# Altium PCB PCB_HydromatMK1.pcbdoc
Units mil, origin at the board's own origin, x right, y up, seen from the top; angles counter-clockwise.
Board outline 5065 x 4705 mil, 2 copper layers (Top Layer, Bottom Layer); 78 components, 51 nets, 249 pads, 533 vias.
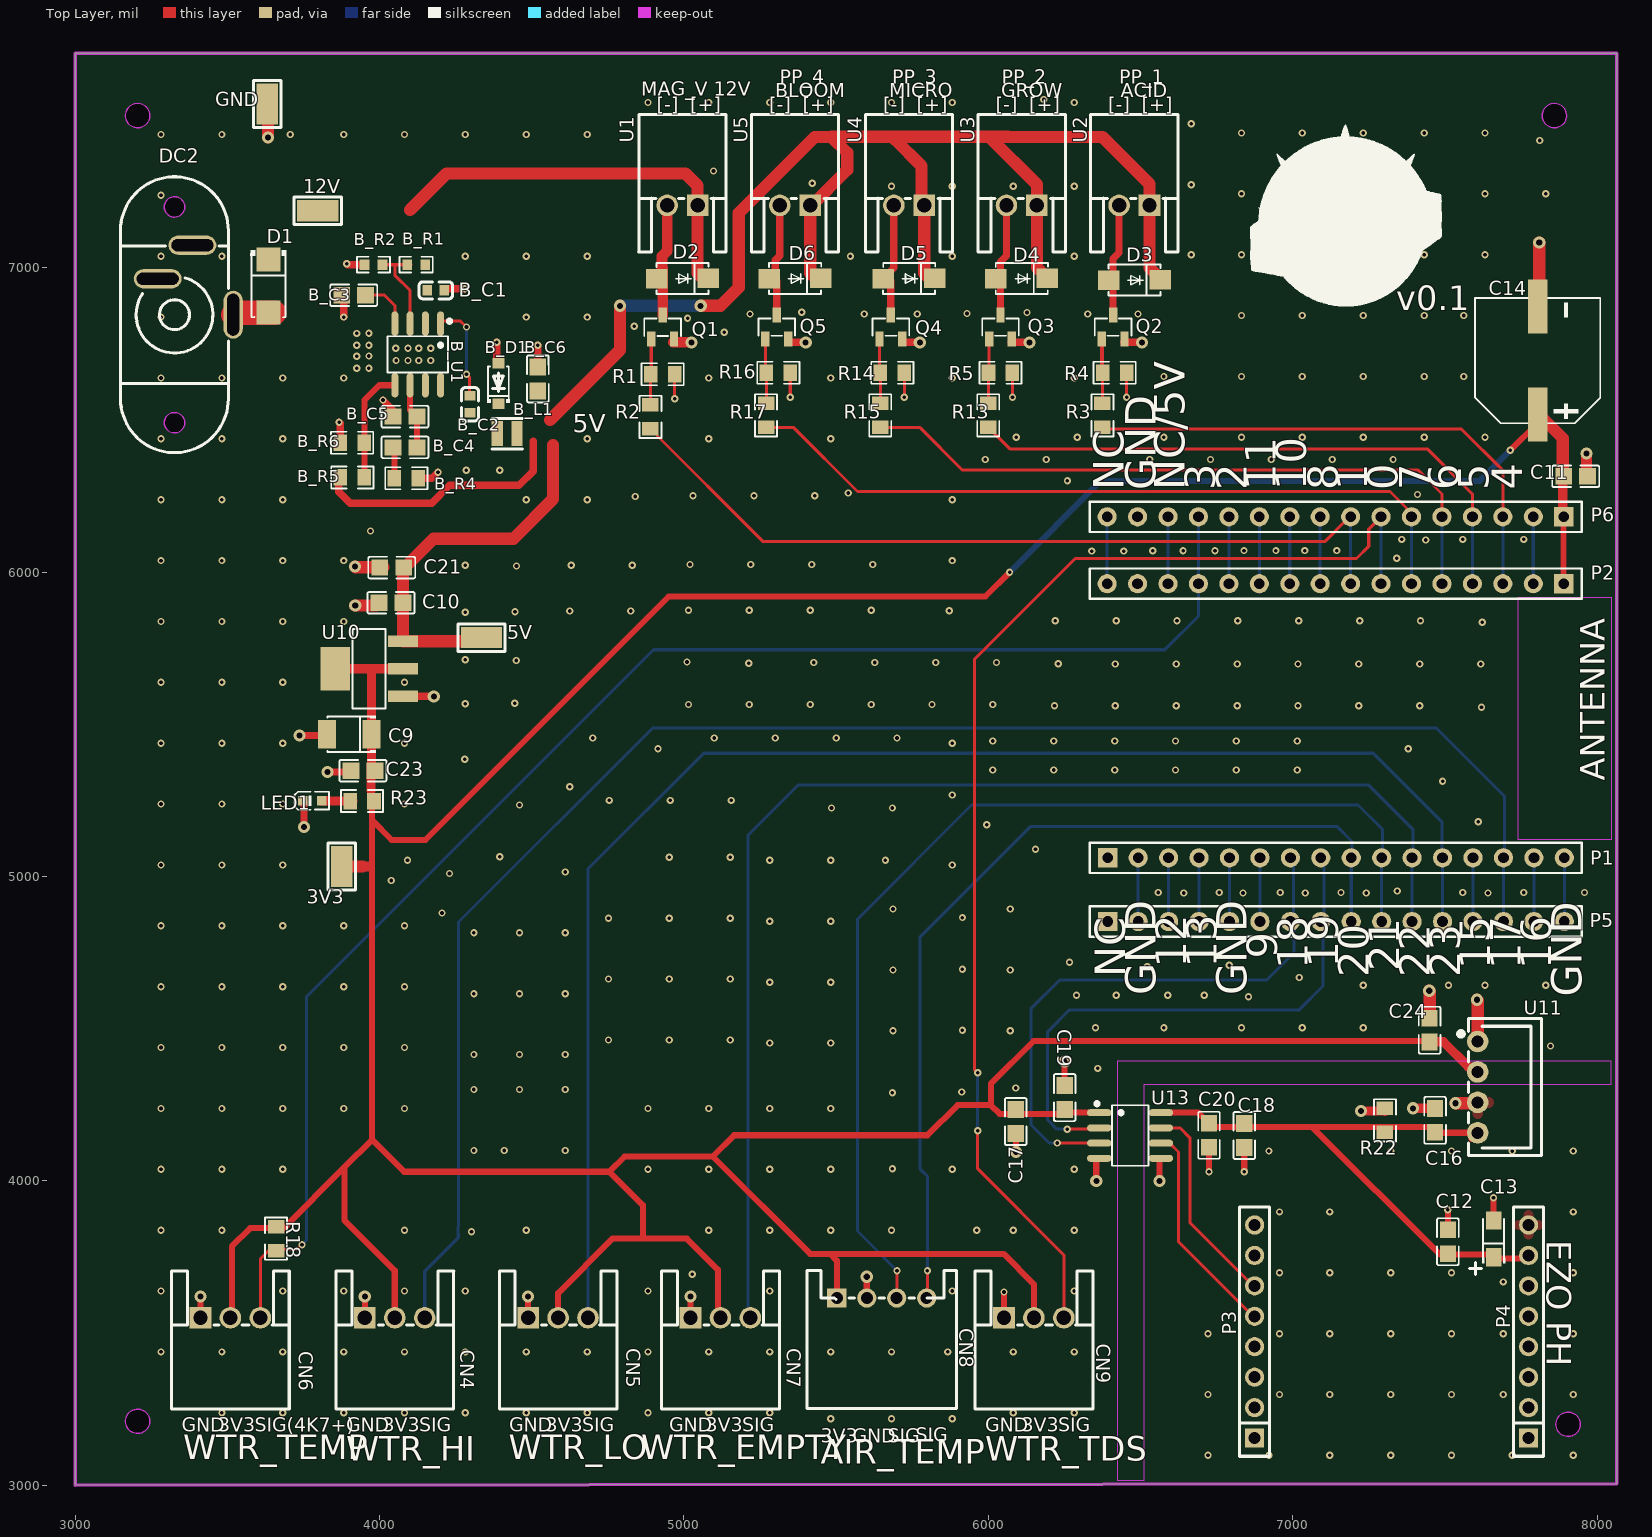
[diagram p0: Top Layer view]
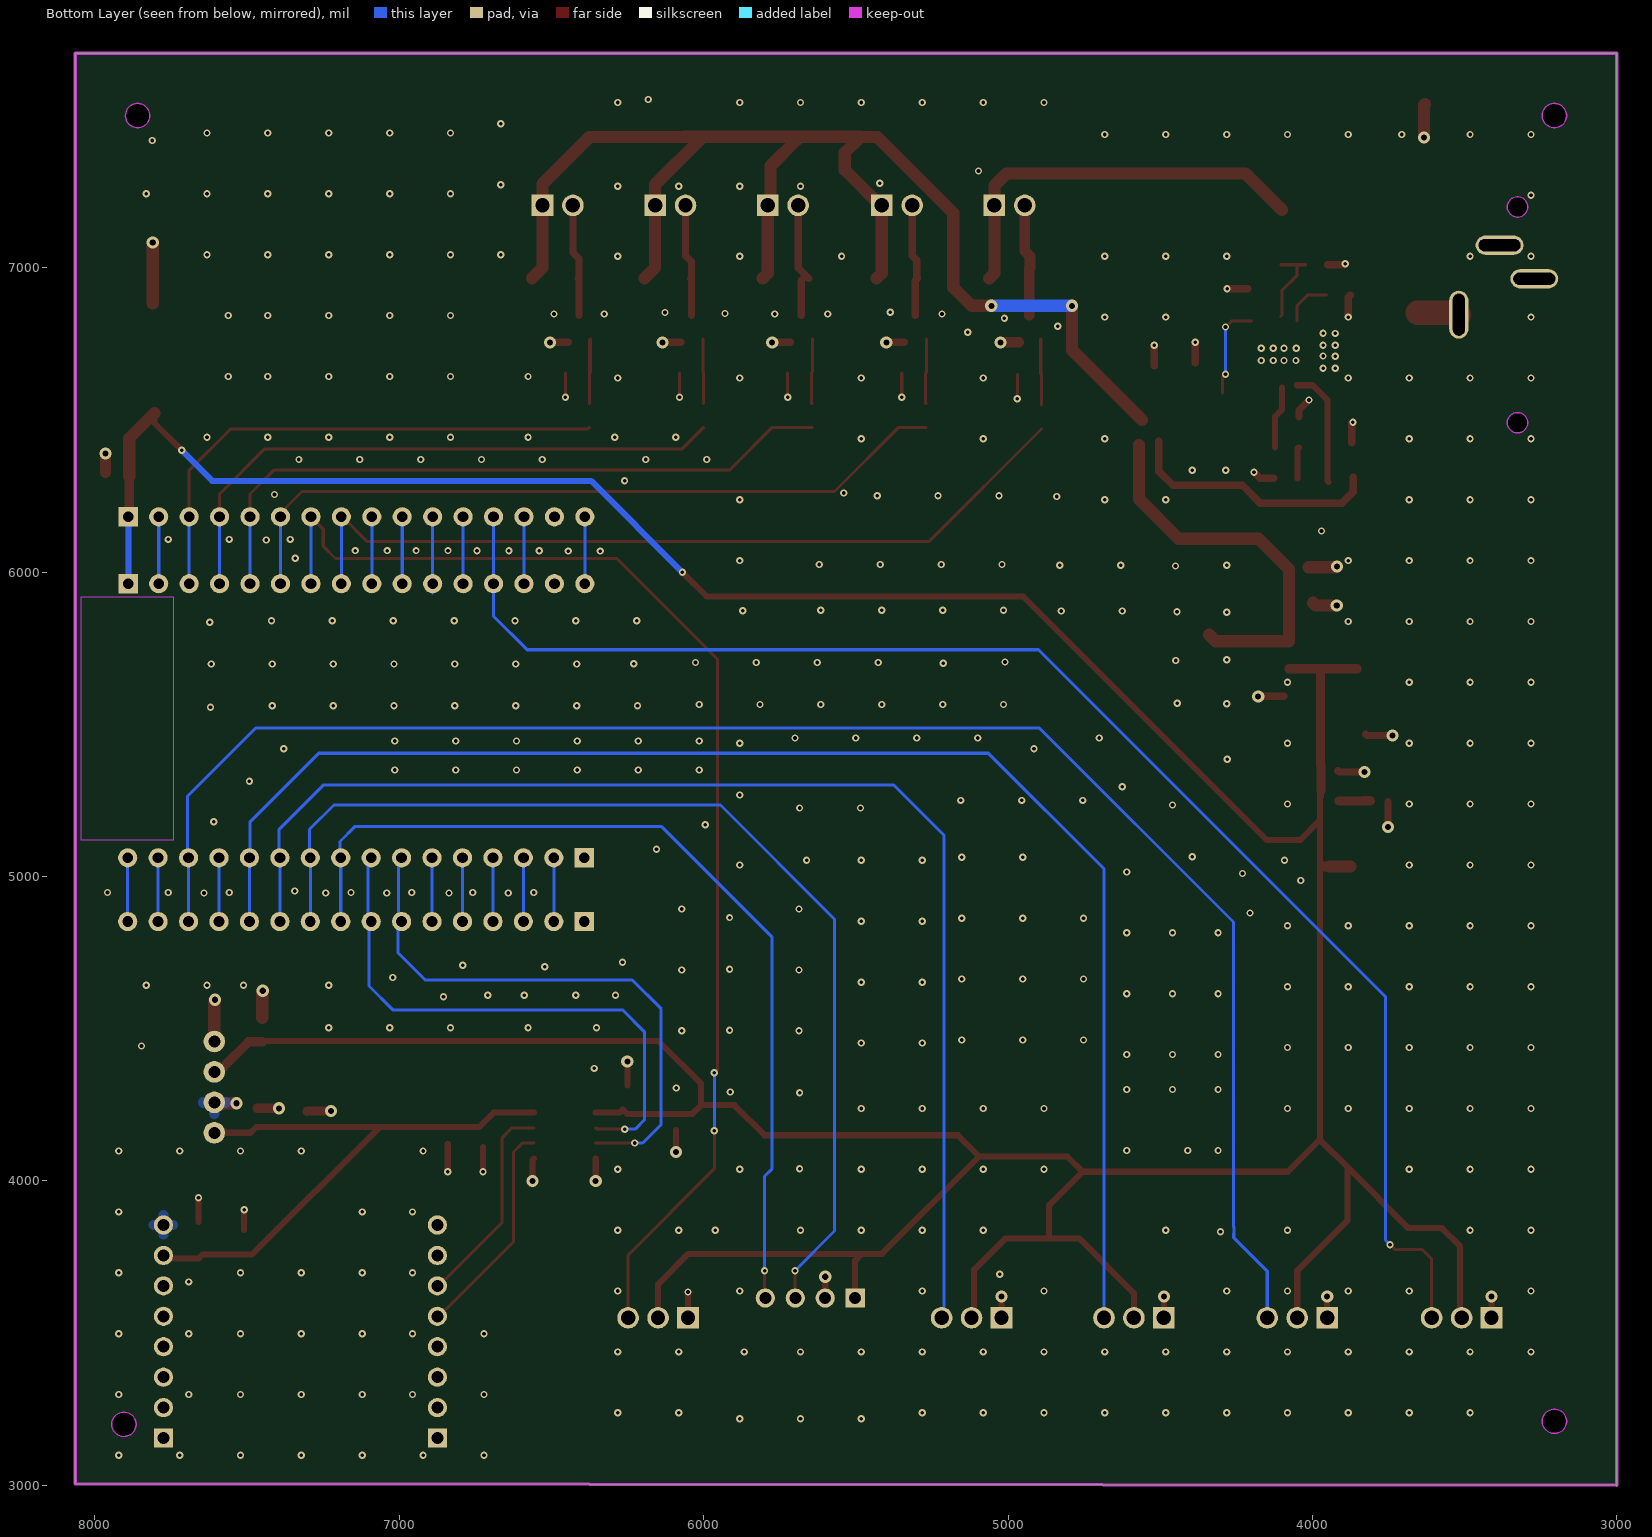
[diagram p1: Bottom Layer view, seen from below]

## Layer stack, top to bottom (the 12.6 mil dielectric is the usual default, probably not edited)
Top Layer: signal copper (thickness not stored)
Dielectric: dielectric 12.6, FR-4, Dk 4.8
Bottom Layer: signal copper (thickness not stored)

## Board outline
3000,3000 8065,3005 8065,7705 3000,7705
cut-out: 7900,7500 cw(c7860,7500) 7820,7500 cw(c7860,7500)
cut-out: 7945,3200 cw(c7905,3200) 7865,3200 cw(c7905,3200)
cut-out: 3245,3210 cw(c3205,3210) 3165,3210 cw(c3205,3210)
cut-out: 3245,7500 cw(c3205,7500) 3165,7500 cw(c3205,7500)

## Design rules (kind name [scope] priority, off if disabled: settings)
BoardOutlineClearance Default [All] p0: genericclearance=10 ignorepadtopadclearanceinfootprint=FALSE except(0: Region-CutoutEdge Arc-SplitContinuation Track-SplitContinuation SMDPad-SplitContinuation THPad-SplitContinuation Via-SplitContinuation Fill-SplitContinuation Poly-SplitContinuation Region-SplitContinuation Text-SplitContinuation; 6.9: Track-CutoutEdge SMDPad-CutoutEdge THPad-CutoutEdge Via-CutoutEdge Fill-CutoutEdge; 15.7: Track-OutlineEdge SMDPad-OutlineEdge THPad-OutlineEdge Via-OutlineEdge Fill-OutlineEdge Region-OutlineEdge Poly-OutlineEdge Text-OutlineEdge)
BoardOutlineClearance 12V [All] p0: genericclearance=10 ignorepadtopadclearanceinfootprint=FALSE except(0: Region-CutoutEdge Arc-SplitContinuation Track-SplitContinuation SMDPad-SplitContinuation THPad-SplitContinuation Via-SplitContinuation Fill-SplitContinuation Poly-SplitContinuation Region-SplitContinuation Text-SplitContinuation; 6.9: Track-OutlineEdge SMDPad-OutlineEdge THPad-OutlineEdge Via-OutlineEdge Fill-OutlineEdge Region-OutlineEdge Poly-OutlineEdge Text-OutlineEdge; 11.1: Track-CutoutEdge SMDPad-CutoutEdge THPad-CutoutEdge Via-CutoutEdge Fill-CutoutEdge)
BoardOutlineClearance GND [All] p0: genericclearance=10 ignorepadtopadclearanceinfootprint=FALSE except(0: Region-CutoutEdge Arc-SplitContinuation Track-SplitContinuation SMDPad-SplitContinuation THPad-SplitContinuation Via-SplitContinuation Fill-SplitContinuation Poly-SplitContinuation Region-SplitContinuation Text-SplitContinuation; 6: Track-CutoutEdge SMDPad-CutoutEdge THPad-CutoutEdge Via-CutoutEdge Fill-CutoutEdge; 6.9: Track-OutlineEdge SMDPad-OutlineEdge THPad-OutlineEdge Via-OutlineEdge Fill-OutlineEdge Region-OutlineEdge Poly-OutlineEdge Text-OutlineEdge)
Clearance Default [(InNet('GPIO4') OR InNet('GPIO5') OR InNet('3V3') OR InNet('GPIO22') OR InNet('GPIO2') OR InNet('GPIO3') OR InNet('GPIO11') OR InNet('GPIO10') OR InNet('GPIO8') OR InNet('GPIO1') OR InNet('GPIO18') OR InNet('GPIO0') OR InNet('GPIO21') OR InNet('GPIO23') OR InNet('GPIO13') OR InNet('GPIO12') OR InNet('GPIO9') OR InNet('GPIO19') OR InNet('GPIO7') OR InNet('GPIO6') OR InNet('GPIO16') OR InNet('GPIO17') OR InNet('GPIO15') OR InNet('GPIO20') OR InNet('5V') OR InNet('RST') OR InNet('$1N1609') OR InNet('3V3_ISO') OR InNet('GND_ISO') OR InNet('$1N3521') OR InNet('$1N63') OR InNet('$1N3479') OR InNet('$1N27') OR InNet('$1N3487') OR InNet('$1N1') OR InNet('$1N13') OR InNet('$1N3439') OR InNet('$1N20') OR InNet('$1N24') OR InNet('$1N28') OR InNet('$1N9552') OR InNet('BOOT') OR InNet('PH') OR InNet('SS') OR InNet('COMP') OR InNet('EN') OR InNet('VSENSE') OR InNet('GPIO18_ISO') OR InNet('GPIO19_ISO'))] p1: gap=7 ignorepadtopadclearanceinfootprint=FALSE except(0: Region-Region; 6.9: Track-SMDPad SMDPad-SMDPad SMDPad-THPad Track-Via SMDPad-Via THPad-Via Track-Fill SMDPad-Fill THPad-Fill Via-Fill Fill-Fill Track-Region SMDPad-Region THPad-Region Via-Region Fill-Region Track-Poly SMDPad-Poly THPad-Poly Via-Poly Fill-Poly Region-Poly Poly-Poly Track-Text SMDPad-Text THPad-Text Via-Text Fill-Text Region-Text Poly-Text Text-Text Track-Hole SMDPad-Hole THPad-Hole Via-Hole Fill-Hole Region-Hole Poly-Hole Text-Hole Sheet-Hole; 7.9: Track-Track; 9.8: THPad-THPad; 11.8: Track-THPad Via-Via; 15.7: Track-Sheet SMDPad-Sheet THPad-Sheet Via-Sheet Fill-Sheet Region-Sheet Poly-Sheet Text-Sheet)
Clearance 12V [(InNet('12V'))] p1: gap=7 ignorepadtopadclearanceinfootprint=FALSE except(0: Region-Region; 6.9: Track-Sheet SMDPad-Sheet THPad-Sheet Via-Sheet Fill-Sheet Region-Sheet Poly-Sheet Text-Sheet Sheet-Hole; 11.1: Track-Track Track-SMDPad SMDPad-SMDPad Track-THPad SMDPad-THPad THPad-THPad Track-Via SMDPad-Via THPad-Via Via-Via Track-Fill SMDPad-Fill THPad-Fill Via-Fill Fill-Fill Track-Region SMDPad-Region THPad-Region Via-Region Fill-Region Track-Poly SMDPad-Poly THPad-Poly Via-Poly Fill-Poly Region-Poly Poly-Poly Track-Text SMDPad-Text THPad-Text Via-Text Fill-Text Region-Text Poly-Text Text-Text Track-Hole SMDPad-Hole THPad-Hole Via-Hole Fill-Hole Region-Hole Poly-Hole Text-Hole)
Clearance GND [(InNet('GND'))] p1: gap=7 ignorepadtopadclearanceinfootprint=FALSE except(0: Region-Region; 6: Track-Track Track-SMDPad SMDPad-SMDPad Track-THPad SMDPad-THPad THPad-THPad Track-Via SMDPad-Via THPad-Via Via-Via Track-Fill SMDPad-Fill THPad-Fill Via-Fill Fill-Fill Track-Region SMDPad-Region THPad-Region Via-Region Fill-Region Track-Poly SMDPad-Poly THPad-Poly Via-Poly Fill-Poly Region-Poly Poly-Poly Track-Text SMDPad-Text THPad-Text Via-Text Fill-Text Region-Text Poly-Text Text-Text Track-Hole SMDPad-Hole THPad-Hole Via-Hole Fill-Hole Region-Hole Poly-Hole Text-Hole; 6.9: Track-Sheet SMDPad-Sheet THPad-Sheet Via-Sheet Fill-Sheet Region-Sheet Poly-Sheet Text-Sheet Sheet-Hole)
DiffPairsRouting differentialPair [All] p1: maxuncoupledlength=10 minlimit=6 maxlimit=6 mostfreqgap=6 toplayer_minwidth=5 toplayer_prefwidth=10 toplayer_maxwidth=100 bottomlayer_minwidth=5 bottomlayer_prefwidth=10 bottomlayer_maxwidth=100
PasteMaskExpansion Common [All] p1: expansion=0
PlaneConnect Default [All] p1: planeconnectstyle=Relief reliefexpansion=20 reliefentries=4 reliefconductorwidth=0 reliefairgap=10
PlaneConnect 12V [All] p1: planeconnectstyle=Relief reliefexpansion=20 reliefentries=4 reliefconductorwidth=0 reliefairgap=10
PlaneConnect GND [All] p1: planeconnectstyle=Relief reliefexpansion=20 reliefentries=4 reliefconductorwidth=0 reliefairgap=10
PolygonConnect Default [All] p1: connectstyle=Direct reliefentries=4 reliefconductorwidth=0 polygonreliefangle="90 Angle" airgapwidth=10
PolygonConnect 12V [All] p1: connectstyle=Direct reliefentries=4 reliefconductorwidth=0 polygonreliefangle="90 Angle" airgapwidth=10
PolygonConnect GND [All] p1: connectstyle=Direct reliefentries=4 reliefconductorwidth=0 polygonreliefangle="90 Angle" airgapwidth=10
PolygonConnect gge52942 [All] p1: connectstyle=Relief reliefentries=4 reliefconductorwidth=0 polygonreliefangle="90 Angle" airgapwidth=10
RoutingVias Default [All] p1: viastyle="Through Hole" holewidth=12.008 minholewidth=12.008 maxholewidth=2362 width=24.016 minwidth=24.016 maxwidth=3938
RoutingVias 12V [All] p1: viastyle="Through Hole" holewidth=23.622 minholewidth=23.622 maxholewidth=2362 width=47.244 minwidth=47.244 maxwidth=3938
RoutingVias GND [All] p1: viastyle="Through Hole" holewidth=12.008 minholewidth=12.008 maxholewidth=2362 width=24.016 minwidth=24.016 maxwidth=3938
SolderMaskExpansion Common [All] p1: useseparateexpansions=TRUE expansion=2 expansionbottom=2
Width Default [All] p1: maxlimit=1000 minlimit=10 preferedwidth=10
Width 12V [All] p1: maxlimit=40 minlimit=30 preferedwidth=35
Width GND [All] p1: maxlimit=1000 minlimit=10 preferedwidth=10
Width 5V [All] p1: maxlimit=100 minlimit=5 preferedwidth=24
Width 3V3 [All] p1: maxlimit=100 minlimit=5 preferedwidth=20

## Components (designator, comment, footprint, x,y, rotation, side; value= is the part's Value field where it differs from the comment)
3V3 "5017_C238130" TEST-SMD_L2.7-W1.0 3875.38,5032.6 r270 top
5V "5017_C238130" TEST-SMD_L2.7-W1.0 4335,5785 r0 top
12V "5017_C238130" TEST-SMD_L2.7-W1.0 3797.05,7187.77 r0 top
B_C1 "CL10A106MO8NQNC" C0603 4184.82,6925.85 r180 top
B_C2 "100nF" C0603 4297.16,6551.49 r90 top
B_C3 "8.2nF" C0805 3915,6910 r0 top
B_C4 "CL21B102KBCNNNC" C0805 4083.74,6410 r0 top
B_C5 "0805CG240J500NT" C0805 4083.56,6510.85 r0 top
B_C6 "10uF" C0805 4520,6635 r270 top
B_D1 "SS24FL" SOD-123_L2.6-W1.6-LS3.5-RD 4390.37,6620.37 r90 top
B_L1 "6.8uH" IND-SMD_L2.5-W2.0_FTC252010S 4419.19,6455.22 r0 top
B_R1 "0603WAF1693T5E" R0603 4120.37,7010.37 r0 top
B_R2 "39.2kΩ" R0603 3980,7010 r0 top
B_R4 "45.3kΩ" R0805 4087.99,6308.33 r180 top
B_R5 "10.2kΩ" R0805 3910.37,6311.29 r180 top
B_R6 "FRC0805J103TS" R0805 3910,6425 r0 top
B_U1 "TPS54232DR" SOIC-8_L4.9-W3.9-P1.27-LS6.0-BL 4125.37,6715.37 r180 top
C9 "TAJB226K016RNJ" CASE-B_3528 3900.38,5467.6 r180 top
C10 "10uF" C0805 4037.66,5899.23 r0 top
C11 "CC0805KRX7R9BB104" C0805 7930,6315 r180 top
C12 "CC0805KRX7R9BB104" C0805 7510,3800 r270 top
C13 "TAJA106K016RNJ" CAP-SMD_L3.2-W1.6-RD-C7171 7660.24,3809.76 r90 top
C14 "RVT1E471M1010" CAP-SMD_BD10.0-L10.3-W10.3-LS11.0-FD 7805,6695 r90 top
C16 "GRM21BR71A106KE51L" C0805 7468,4199 r270 top
C17 "CC0805KRX7R9BB104" C0805 6090,4195 r90 top
C18 "CC0805KRX7R9BB104" C0805 6841.02,4149.05 r90 top
C19 "GRM21BR71A106KE51L" C0805 6251.02,4273.39 r270 top
C20 "GRM21BR71A106KE51L" C0805 6725.16,4149.82 r90 top
C21 "CC0805KRX7R9BB104" C0805 4040,6015 r0 top
C23 "CC0805KRX7R9BB104" C0805 3945.38,5347.6 r0 top
C24 "GRM21BR71A106KE51L" C0805 7450,4495 r90 top
CN4 "S3B-XH-A-1(LF)(SN)" CONN-TH_S3B-XH-A-1-LF-SN 4050,3550 r180 top
CN5 "S3B-XH-A-1(LF)(SN)" CONN-TH_S3B-XH-A-1-LF-SN 4586.46,3550 r180 top
CN6 "S3B-XH-A-1(LF)(SN)" CONN-TH_S3B-XH-A-1-LF-SN 3510,3550 r180 top
CN7 "S3B-XH-A-1(LF)(SN)" CONN-TH_S3B-XH-A-1-LF-SN 5120,3550 r180 top
CN8 "S4B-XH-A(LF)(SN)" CONN-TH_S4B-XH-A-LF-SN 5650,3615 r180 top
CN9 "S3B-XH-A-1(LF)(SN)" CONN-TH_S3B-XH-A-1-LF-SN 6150,3550 r180 top
D1 "SS54" SMA_L4.3-W2.6-LS5.1-RD 3635,6940 r270 top
D2 "SS24" SMA_L4.3-W2.6-LS5.0-FD 4995,6965 r0 top
D3 "SS24" SMA_L4.3-W2.6-LS5.0-FD 6480,6960 r0 top
D4 "SS24" SMA_L4.3-W2.6-LS5.0-FD 6109.72,6965 r0 top
D5 "SS24" SMA_L4.3-W2.6-LS5.0-FD 5739.72,6965 r0 top
D6 "SS24" SMA_L4.3-W2.6-LS5.0-FD 5365,6965 r0 top
DC2 "DC-018-2.5A-2.5" DC-IN-TH_DC-018 3395,6960 r180 top
GND "5017_C238130" TEST-SMD_L2.7-W1.0 3631.02,7538.38 r270 top
LED1 "XL-1608UGC-04" LED0603-RD_GREEN 3778.77,5248.94 r0 top
P1 "ZX-PM2.54-1-16PY" HDR-TH_16P-P2.54-V-F-1 7142.54,5061.4 r0 top
P2 "ZX-PM2.54-1-16PY" HDR-TH_16P-P2.54-V-F-1 7140.55,5961.91 r180 top
P3 "2.54-1*8P母环保" HDR-TH_8P-P2.54-V-F_2 6875,3505 r90 top
P4 "2.54-1*8P母环保" HDR-TH_8P-P2.54-V-F_2 7775,3505 r90 top
P5 "ZX-PM2.54-1-16PY" HDR-TH_16P-P2.54-V-F-1 7142.54,4851.9 r0 top
P6 "ZX-PM2.54-1-16PY" HDR-TH_16P-P2.54-V-F-1 7140.55,6181.91 r180 top
Q1 "IRLML6244TRPBF" SOT-23-3_L2.9-W1.3-P1.90-LS2.4-BR 4930,6804.99 r270 top
Q2 "IRLML6244TRPBF" SOT-23-3_L2.9-W1.3-P1.90-LS2.4-BR 6410,6805 r270 top
Q3 "IRLML6244TRPBF" SOT-23-3_L2.9-W1.3-P1.90-LS2.4-BR 6040,6805 r270 top
Q4 "IRLML6244TRPBF" SOT-23-3_L2.9-W1.3-P1.90-LS2.4-BR 5680,6805 r270 top
Q5 "IRLML6244TRPBF" SOT-23-3_L2.9-W1.3-P1.90-LS2.4-BR 5305,6805 r270 top
R1 "0805W8F1002T5E" R0805 4930,6650 r180 top
R2 "0805W8F1000T5E_C17408" R0805 4890,6510 r90 top
R3 "0805W8F1000T5E_C17408" R0805 6375,6515 r270 top
R4 "0805W8F1002T5E" R0805 6415,6655 r180 top
R5 "0805W8F1002T5E" R0805 6040,6655 r180 top
R13 "0805W8F1000T5E_C17408" R0805 6000,6515 r270 top
R14 "0805W8F1002T5E" R0805 5685,6655 r180 top
R15 "0805W8F1000T5E_C17408" R0805 5645,6515 r270 top
R16 "0805W8F1002T5E" R0805 5310,6655 r180 top
R17 "0805W8F1000T5E_C17408" R0805 5270,6515 r90 top
R18 "0805W8F4701T5E" R0805 3660,3810 r270 top
R22 "0805W8F1000T5E_C17408" R0805 7303,4199 r270 top
R23 "FRC0805J102 TS" R0805 3942.35,5247.96 r0 top
U1 "S2B-XH-A-1(LF)(SN)" CONN-TH_S2B-XH-A-1-LF-SN 4995,7205 r0 top
U2 "S2B-XH-A-1(LF)(SN)" CONN-TH_S2B-XH-A-1-LF-SN 6479.7,7205 r0 top
U3 "S2B-XH-A-1(LF)(SN)" CONN-TH_S2B-XH-A-1-LF-SN 6109.7,7205 r0 top
U4 "S2B-XH-A-1(LF)(SN)" CONN-TH_S2B-XH-A-1-LF-SN 5739.7,7205 r0 top
U5 "S2B-XH-A-1(LF)(SN)" CONN-TH_S2B-XH-A-1-LF-SN 5365,7205 r0 top
U10 "AMS1117-3.3_C347222" SOT-223-4_L6.5-W3.5-P2.30-LS7.0-BR 3965.38,5682.6 r0 top
U11 "B0303S-1WR3_C7468813" PWRM-TH_B0303S-1WR3 7608,4308 r270 top
U13 "ADUM1201ARZ-RL7" SOIC-8_L4.9-W3.9-P1.27-LS6.0-BL 6466,4149.05 r270 top

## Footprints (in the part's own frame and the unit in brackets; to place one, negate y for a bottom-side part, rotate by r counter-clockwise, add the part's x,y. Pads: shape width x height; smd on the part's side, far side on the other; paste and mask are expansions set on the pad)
C0603 [mm]
  rect 0.8x0.9 smd: 1(-0.7,0) 2(0.7,0)
  silkscreen extent -1.39,-0.71 1.39,0.71
C0805 [mm]
  rect 1.41x1.35 smd: 1(-1,0) 2(1,0)
  silkscreen extent -1.96,-0.9 1.96,0.9
CAP-SMD_BD10.0-L10.3-W10.3-LS11.0-FD [mm]
  rect 4.5x1.65 smd: 1(-4.5,0) 2(4.5,0)
  silkscreen extent -5.23,-5.23 5.23,5.23
CAP-SMD_L3.2-W1.6-RD-C7171 [mm]
  rect 1.53x1.296 smd: 1(-1.53,0) 2(1.53,0)
  silkscreen extent -3,-0.95 1.68,2
CASE-B_3528 [mil]
  rect 59.3x93.54 smd: 1(-73.25,0) 2(73.25,0)
  silkscreen extent -87,-61 72,61
CONN-TH_S2B-XH-A-1-LF-SN [mm]
  rect 1.8x1.8 hole 1.2: 1(1.27,0)
  round 1.8 hole 1.2: 2(-1.27,0)
  silkscreen extent -3.65,-3.9 3.64,7.6
CONN-TH_S3B-XH-A-1-LF-SN [mm]
  rect 1.8x1.8 hole 1.2: 1(2.5,0)
  round 1.8 hole 1.2: 2(0,0) 3(-2.5,0)
  silkscreen extent -4.92,-3.9 4.91,7.6
CONN-TH_S4B-XH-A-LF-SN [mm]
  rect 1.6x1.6 hole 1: 1(3.75,0)
  round 1.6 hole 1: 2(1.25,0) 3(-1.25,0) 4(-3.75,0)
  silkscreen extent -6.25,-2.3 6.25,9.2
DC-IN-TH_DC-018 [mm]
  oval 1.6x4 hole 1 slot 3.5 at 90 deg copper offset 0.001,0: 1(-3.151,2.9)
  oval 4x1.6 hole 1 slot 3.5 at 0 deg copper offset -0.001,-0.001: 2(0.251,-2.899)
  oval 4x1.6 hole 1 slot 3.5 at 0 deg copper offset 0,-0.001: 3(3.15,-0.099)
  Board Outline Layer circle w0.005: c1.75,11.913 r0.85
  Board Outline Layer circle w0.005: c1.75,-6.096 r0.85
  Board Outline Layer region: 0.9,11.913 0.984,12.281 1.22,12.577 1.561,12.741 1.939,12.741 2.28,12.577 2.516,12.281 2.6,11.913 2.6,11.913 2.516,11.544 2.28,11.248 1.939,11.084 1.561,11.084 1.22,11.248 0.984,11.544 0.9,11.913
  Board Outline Layer region: 0.9,-6.096 0.984,-5.727 1.22,-5.431 1.561,-5.267 1.939,-5.267 2.28,-5.431 2.516,-5.727 2.6,-6.096 2.6,-6.096 2.516,-6.465 2.28,-6.761 1.939,-6.925 1.561,-6.925 1.22,-6.761 0.984,-6.465 0.9,-6.096
  Multi-Layer board cut-out: 0.9,11.913 0.984,12.281 1.22,12.577 1.561,12.741 1.939,12.741 2.28,12.577 2.516,12.281 2.6,11.913 2.6,11.913 2.516,11.544 2.28,11.248 1.939,11.084 1.561,11.084 1.22,11.248 0.984,11.544 0.9,11.913
  Multi-Layer board cut-out: 0.9,-6.096 0.984,-5.727 1.22,-5.431 1.561,-5.267 1.939,-5.267 2.28,-5.431 2.516,-5.727 2.6,-6.096 2.6,-6.096 2.516,-6.465 2.28,-6.761 1.939,-6.925 1.561,-6.925 1.22,-6.761 0.984,-6.465 0.9,-6.096
  silkscreen extent -2.75,-8.61 6.25,14.41
HDR-TH_8P-P2.54-V-F_2 [mm]
  rect 1.6x1.6 hole 1: 1(-8.89,0)
  round 1.6 hole 1: 2(-6.35,0) 3(-3.81,0) 4(-1.27,0) 5(1.27,0) 6(3.81,0) 7(6.35,0) 8(8.89,0)
  silkscreen extent -10.41,-1.25 10.41,1.25
HDR-TH_16P-P2.54-V-F-1 [mm]
  rect 1.6x1.6 hole 0.9: 1(-19.05,0)
  round 1.6 hole 0.9: 2(-16.51,0) 3(-13.97,0) 4(-11.43,0) 5(-8.89,0) 6(-6.35,0) 7(-3.81,0) 8(-1.27,0) 9(1.27,0) 10(3.81,0) 11(6.35,0) 12(8.89,0) 13(11.43,0) 14(13.97,0) 15(16.51,0) 16(19.05,0)
  silkscreen extent -20.55,-1.27 20.5,1.27
IND-SMD_L2.5-W2.0_FTC252010S [mm]
  rect 0.95x2.1 smd: 1(-0.825,0) 2(0.825,0)
  silkscreen extent -1.27,-1.27 1.27,1.27
LED0603-RD_GREEN [mm]
  rect 0.8x0.8 smd: 1(-0.799,-0.003) 2(0.799,0.003)
  silkscreen extent -1.49,-0.75 1.39,0.76
PWRM-TH_B0303S-1WR3 [mm]
  round 1.8 hole 1: 1(-3.81,0) 2(-1.27,0) 3(1.27,0) 4(3.81,0)
  silkscreen extent -5.72,-1.6 5.71,5.33
R0603 [mil]
  rect 31.75x34.02 smd: 1(-29.66,0) 2(29.66,0)
  silkscreen extent -55,-26 55,26
R0805 [mm]
  rect 1.133x1.377 smd: 1(-1,0) 2(1,0)
  silkscreen extent -1.76,-0.92 1.76,0.92
SMA_L4.3-W2.6-LS5.0-FD [mm]
  rect 1.8x1.62 smd: 1(2.15,0.009) 2(-2.15,-0.009)
  silkscreen extent -2.17,-1.32 2.19,1.29
SMA_L4.3-W2.6-LS5.1-RD [mm]
  rect 2x2 smd: 1(-2.2,0) 2(2.2,0)
  silkscreen extent -2.98,-1.5 2.6,1.5
SOD-123_L2.6-W1.6-LS3.5-RD [mm]
  rect 0.88x0.99 smd: 1(-1.692,0) 2(1.692,0)
  silkscreen extent -1.63,-0.94 1.41,0.94
SOIC-8_L4.9-W3.9-P1.27-LS6.0-BL [mm]
  oval 0.588x2.045 smd: 1(-1.905,-2.57) 2(-0.635,-2.57) 3(0.635,-2.57) 4(1.905,-2.57) 5(1.905,2.57) 6(0.635,2.57) 7(-0.635,2.57) 8(-1.905,2.57)
  silkscreen extent -2.8,-2.92 2.53,1.52
SOT-23-3_L2.9-W1.3-P1.90-LS2.4-BR [mm]
  rect 1.25x0.7 smd: 1(1,-0.95) 2(1,0.95) 3(-1,0)
  silkscreen extent -0.73,-1.53 0.73,1.53
SOT-223-4_L6.5-W3.5-P2.30-LS7.0-BR [mm]
  rect 2.47x0.98 smd: 1(2.835,-2.3) 2(2.835,0) 3(2.835,2.3)
  rect 2.47x3.6 smd: 4(-2.835,0)
  silkscreen extent -1.37,-3.33 1.37,3.33
TEST-SMD_L2.7-W1.0 [mm]
  rect 3.43x1.78 smd: 1(0,0)
  silkscreen extent -1.97,-1.14 1.97,1.14

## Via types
v1: diameter 24.02, hole 12.01, Top Layer to Bottom Layer, 482 vias
v2: diameter 40, hole 20, Top Layer to Bottom Layer, 30 vias
v3: diameter 24, hole 12, Top Layer to Bottom Layer, 21 vias

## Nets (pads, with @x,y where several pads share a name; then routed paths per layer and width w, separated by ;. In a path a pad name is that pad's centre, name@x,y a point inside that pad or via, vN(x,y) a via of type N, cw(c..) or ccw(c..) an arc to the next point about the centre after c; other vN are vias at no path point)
3V3: 3V3.1 C9.1 C11.2 C14.1 C17.2 C19.2 C23.2 C24.1 CN4.2 CN5.2 CN6.2 CN7.2 CN8.1 CN9.2 P2.1 P6.1 R18.1 R23.2 U10.2 U10.4 U11.2 U13.1 | length 15470.6
  Top Layer w18.71: R23.2@3972.01,5262.96 R23.2@3975.38,5259.59
  Top Layer w20: CN6.2 3515,3554.98 3515,3785 3575,3845 3685.34,3845 3884.59,4044.25 ; R23.2@3972.01,5262.96 3972.01,5282.96 3975.38,5279.59 3975.38,5259.59 3975.38,5184.46 ; C23.2@3972.01,5346.68 C23.2@3972.94,5347.6 ; C9.1@3972.94,5466.91 C9.1 ; CN4.2 4050.01,3704.99 3884.59,3870.41 3884.59,4044.25 ; CN5.2 4586.48,3631.47 4765,3810 4865,3810 ; CN7.2@5111.48,3549.99 5111.48,3708.53 5010,3810 4865,3810 ; CN8.1@5502.36,3621.34 5502.36,3737.64 5480.17,3759.83 ; v3(6070,6000) 5990,5920 4950,5920 4150,5120 4039.84,5120 3975.38,5184.46 ; CN9.2 6150.01,3659.99 6050.17,3759.83 5480.17,3759.83 ; U13.1@6354.82,4224.05 6275.98,4224.05 6266.02,4234.02 6252,4220 6037.63,4220 6008.54,4249.09 ; C24.1@7450.44,4457.07 7448.42,4459.09 6148.54,4459.09 6008.54,4319.09 6008.54,4249.09 ; v3(7715,6400) 7805,6490 C14.1@7805,6521.97 ; P2.1@7890.55,5976.91 P6.1@7890.55,6176.91 ; 3884.59,4044.25 3975.38,4135.04 ; 3975.38,4135.04 4080.41,4030 4755,4030 ; 3975.38,4135.04 3975.38,5184.46 ; 4755,4030 4865,3920 4865,3810 ; 4755,4030 4805,4080 5095,4080 ; 5095,4080 5415.17,3759.83 5480.17,3759.83 ; 5095,4080 5165,4150 5800,4150 5899.09,4249.09 6008.54,4249.09
  Top Layer w30: U10.4 3975.77,5682.6 ; 3972.01,5282.96 3972.01,5346.68 3972.01,5366.68 3972.94,5367.6 3972.94,5466.91 3972.94,5476.91 3973.63,5477.6 3973.63,5680.46 3975.77,5682.6 ; U10.2 3975.77,5682.6 ; C24.1@7450.44,4457.07 7495.44,4457.07 7576.12,4376.39 7576.12,4373.88 ; U11.2@7587.12,4373.88 7603,4358 U11.2 ; C11.2@7887.44,6315 7887.44,6190.02 P6.1@7890.55,6186.91
  Top Layer w32: 3945,5032.6 3965,5032.6
  Top Layer w40: 3V3.1 3945,5032.6 ; C14.1@7805,6521.97 7887.44,6439.53 C11.2@7887.44,6315
  Bottom Layer w20: v3(6070,6000) 6370,6300 7615,6300 v3(7715,6400) ; P2.1 P6.1
3V3_ISO: C12.2 C13.1 C16.2 C18.2 C20.2 P4.7 R22.2 U11.4 U13.8 | length 1999.8
  Top Layer w20: U13.8@6557.18,4224.05 6690.3,4224.05 C20.2 6737.74,4176.61 7065.11,4176.61 ; 7065,4176.72 7065.11,4176.61 ; U11.4@7588,4138 U11.4 7489.63,4158 7471.02,4176.61 7065.11,4176.61 ; P4.7 7764.52,3744.52 7660.24,3744.52 7647.32,3757.44 7484.28,3757.44 7065.11,4176.61
5V: 5V.1 B_C6.2 B_L1.2 B_R5.2 C10.2 C21.2 D3.1 D4.1 D5.1 D6.1 U2.1 U3.1 U4.1 U5.1 U10.3 | length 6680.9
  Top Layer w24: B_R5.2@3866,6311.29 3866,6264 3903.71,6226.29 4171.29,6226.29 4230,6285 4458.03,6285 4505,6331.97 4505,6430
  Top Layer w40: 5V.1@4340,5795 4318.15,5773.15 U10.3 C10.2 4076.99,6009.43 4177.56,6110 4440,6110 4570,6240 4570,6417.5 ; 4560,6500 4790,6730 v2(4790,6875) ; v2(5055,6875) 5120,6875 5180,6935 5180,7180 5430,7430 5485,7430 ; D6.1@5431.93,6965.37 5415,6982.3 5415,7200 5536.72,7321.72 5536.72,7378.28 5485,7430 ; 5694.27,7420.73 5780.48,7334.52 5780.48,7209.52 5789.7,7200.3 5789.7,6981.94 D5.1@5806.65,6965 ; D4.1 6159.7,7000.03 6159.7,7190 6159.7,7273.78 6002.76,7430.73 ; D3.1@6564.36,6965.37 6529.7,7000.03 6529.7,7190 6529.7,7275.3 6375.59,7429.41 6066.03,7429.41 6064.71,7430.73 6002.76,7430.73 ; 5485,7430 5485.73,7430.73 6002.76,7430.73
  Bottom Layer w40: v2(4790,6875) v2(5055,6875)
12V: 12V.1 B_C1.2 B_R1.2 B_U1.2 D1.1 D2.1 U1.1 | length 1323.3
  Top Layer w40: 4100,7190 4220,7310 5005,7310 5045,7270 U1.1 5045,6981.93 D2.1@5061.93,6965
$1N1: D1.2 DC2.1 | length 138.6
  Top Layer w80: DC2.1 3525.26,6852.06 D1.2@3655,6852.06
$1N13: D2.2 Q1.3 U1.2 | length 371.2
  Top Layer w10: Q1.3@4928.07,6846.29 Q1.3
  Top Layer w35: Q1.3 4930,6998.07 4928.07,7000 4928.07,7038.07 4945,7055 U1.2
$1N20: D4.2 Q3.3 U3.2 | length 371.1
  Top Layer w24: Q3.3 6040,6962.21 6042.79,6965 6040,6967.78 6040,7020 6059.7,7039.7 U3.2
$1N24: D5.2 Q4.3 U4.2 | length 502
  Top Layer w10: D5.2@5672.79,6965 5672.79,6851.58 Q4.3
  Top Layer w24: D5.2 5689.7,6999.26 U4.2 ; D5.2@5672.79,6965 5680,6957.78 Q4.3
$1N27: Q4.1 R14.2 R15.1 | length 213.7
  Top Layer w10: Q4.1 5642.6,6658.03 R14.2 R15.1@5645.63,6560 ; R15.1 5645.63,6555 R15.1@5645.63,6560 ; R15.1@5645,6559.37 R15.1@5645.63,6560
$1N28: D6.2 Q5.3 U5.2 | length 370.5
  Top Layer w24: Q5.3 5305,6958.07 5298.07,6965 5298.07,6970 5300,6971.93 5300,7025 5315,7040 U5.2
$1N63: Q2.1 R3.1 R4.2 | length 324.7
  Top Layer w10: R3.1 6375.63,6555 R4.2 ; R4.2 6375.63,6762.6 Q2.1 6372.6,6658.03 R4.2
$1N1609: B_C4.1 B_R4.2 | length 103.4
  Top Layer w20: B_C4.1 4048.62,6405.75 B_R4.2
$1N3439: D3.2 Q2.3 U2.2 | length 371.1
  Top Layer w24: Q2.3 6410,6962.21 6412.79,6965 6410,6967.79 6410,7030 6429.7,7049.7 U2.2
$1N3479: Q3.1 R5.2 R13.1 | length 308.2
  Top Layer w10: R13.1 6000.63,6555 R5.2 ; R13.1@6000,6559.37 6000,6654.37 R5.2 ; Q3.1 6002.6,6656.97 R5.2
$1N3487: Q5.1 R16.2 R17.2 | length 213.7
  Top Layer w10: Q5.1 5267.6,6658.03 R16.2 R17.2@5270.63,6560 ; R17.2 5270.63,6555 R17.2@5270.63,6560 ; R17.2@5270,6559.37 R17.2@5270.63,6560
$1N3521: Q1.1 R1.2 R2.2 | length 226
  Top Layer w10: R2.2 4890.63,6550 R2.2@4890.63,6560 ; R2.2@4890,6559.37 R2.2@4890.63,6560 ; Q1.1 R1.2@4892.6,6656.97 ; R2.2@4890.63,6560 R1.2 ; R1.2 4892.6,6651.97 R1.2@4892.6,6656.97 ; R1.2 4890.63,6655 R1.2@4892.6,6656.97
$1N9552: LED1.2 R23.1 | length 104.5
  Top Layer w10: R23.1@3911.57,5249.08 R23.1@3912.69,5247.96
  Top Layer w30: LED1.2 3830.24,5249.08 3831.36,5247.96 R23.1@3912.69,5247.96
BOOT: B_C2.2 B_U1.1 | length 314.3
  Top Layer w10: B_U1.1@4200.37,6824.51 4266.22,6824.51 v1(4285.37,6805.37) ; v1(4285.37,6650.33) 4295,6640.69 B_C2.2@4295,6587.95
  Bottom Layer w10: v1(4285.37,6650.33) v1(4285.37,6805.37)
COMP: B_C4.2 B_C5.2 B_U1.6 | length 205.4
  Top Layer w20: B_U1.6@4100.37,6606.21 4100.37,6533.42 B_C5.2 ; B_C4.2 B_C5.2@4123.11,6510.68
EN: B_R1.1 B_R2.2 B_U1.3 | length 274.2
  Top Layer w10: B_R2.2@4022.41,7010.37 4022.77,7010 4050.37,7010 ; 4049.63,7010.37 4050,7010 ; B_R1.1@4103.33,7010.37 4102.96,7010 4050.37,7010 ; B_U1.3@4105,6840.18 4100,6845.18 4100,6925.73 4050.37,6975.37 4050.37,7010
GND: B_C1.1 B_C3.1 B_C5.1 B_C6.1 B_D1.2 B_R2.1 B_R4.1 B_R6.1 B_U1.7 C9.2 C10.1 C11.1 C14.2 C17.1 C19.1 C21.1 C23.1 C24.2 CN4.1 CN5.1 CN6.1 CN7.1 CN8.2 CN9.1 DC2.2 DC2.3 GND.1 LED1.1 P1.2 P1.5 P1.16 P2.15 P5.2 P5.5 P5.16 P6.15 Q1.2 Q2.2 Q3.2 Q4.2 Q5.2 R1.1 R4.1 R5.1 R14.1 R16.1 U10.1 U11.1 U13.4 | length 3664.1
  Top Layer w10: v3(4969.37,6570) R1.1 ; v3(5349.37,6575) R16.1 ; v3(5724.37,6575) R14.1 ; v3(6079.37,6575) R5.1 ; v3(6454.37,6575) R4.1
  Top Layer w20: CN6.1 v2(3411.57,3620) ; CN4.1 v2(3951.57,3620) ; CN5.1 v2(4488.04,3620.01) ; CN7.1 v2(5021.57,3620) ; CN8.2 v2(5600.78,3685) ; CN9.1 v3(6051.57,3635) ; v2(6091.02,4095) C17.1@6091.02,4166.49 ; C19.1 v2(6251.02,4392.44) ; U13.4@6354.82,4074.05 6354.82,4000.18 v2(6355,4000)
  Top Layer w24: v2(3736.66,5463.37) 3820.72,5463.37 C9.2@3824.95,5467.6 ; v2(3751.5,5162.13) LED1.1@3751.5,5246.18 ; v2(3828.87,5343.37) 3912.93,5343.37 C23.1@3917.16,5347.6 ; v1(3867.01,6492.99) 3870.63,6489.37 B_R6.1 ; B_C3.1 3882.01,6903.62 v1(3882.01,6837.99) ; v1(3892.01,7012.99) 3895,7010 B_R2.1 ; v3(4011.19,6565.49) 4044.19,6532.48 B_C5.1 ; U10.1@4094.15,5591.83 v2(4178.2,5591.83) ; B_R4.1 4172.34,6308.33 v1(4192.01,6327.99) ; B_C1.1@4212.38,6930.85 4280.02,6930.85 v3(4280.39,6931.22) ; v3(4385,6755) 4385.37,6754.63 B_D1.2@4385.37,6687 ; v3(4519.63,6745.43) 4520,6745.06 B_C6.1@4520,6677.42 ; Q5.2@5340,6755 v2(5400,6755) ; Q4.2@5715,6755 v2(5775,6755) ; Q3.2@6075,6755 v2(6135,6755) ; Q2.2@6445,6755 v2(6505,6755)
  Top Layer w35: Q1.2@4965,6754.99 v2(5025,6754.99)
  Top Layer w36: C11.1@7965,6327.44 v2(7965,6390)
  Top Layer w40: GND.1 3633.7,7535.7 v2(3633.7,7427.71) ; v2(3919.33,6018.19) 3921.2,6016.33 C21.1@4012.38,6016.33 ; v2(3920,5890) 3989.05,5890 C10.1 ; v2(7448.74,4624.77) 7450.44,4623.06 C24.2@7450.44,4535.81 ; v2(7606,4595) 7608,4593 U11.1 ; C14.2@7810.14,6882.89 v2(7810.14,7083.01)
  Bottom Layer w10: P5.2@6492.54,4856.89 P1.2@6492.54,5066.38 ; P5.5@6792.54,4856.89 P1.5@6792.54,5066.38 ; P5.16@7892.54,4856.89 P1.16@7892.54,5066.38
  other v1: 5482.01,3217.99 5682.01,3217.99 5882.01,3217.99 3482.01,3237.99 3682.01,3237.99 3882.01,3237.99 4082.01,3237.99 4282.01,3237.99 4482.01,3237.99 4682.01,3237.99 4882.01,3237.99 5082.01,3237.99 5282.01,3237.99 6082.01,3237.99 6282.01,3237.99 3282.01,3437.99 3482.01,3437.99 3682.01,3437.99 3882.01,3437.99 4082.01,3437.99 4282.01,3437.99 4482.01,3437.99 4682.01,3437.99 4882.01,3437.99 5082.01,3437.99 5282.01,3437.99 5482.01,3437.99 5682.01,3437.99 5867.01,3437.99 6082.01,3437.99 6282.01,3437.99 3282.01,3637.99 3682.01,3637.99 3882.01,3637.99 4082.01,3637.99 4282.01,3637.99 4882.01,3637.99 5282.01,3637.99 5882.01,3637.99 6282.01,3637.99 5027.01,3692.99 4302.01,3832.99 3282.01,3837.99 3482.01,3837.99 4082.01,3837.99 4482.01,3837.99 5082.01,3837.99 5282.01,3837.99 5482.01,3837.99 5682.01,3837.99 5962.01,3837.99 6082.01,3837.99 6282.01,3837.99 3282.01,4037.99 3482.01,4037.99 3682.01,4037.99 4882.01,4037.99 5082.01,4037.99 5282.01,4037.99 5482.01,4037.99 5882.01,4037.99 6282.01,4037.99 5685,4040 4310,4100 4410,4100 4610,4100 3282.01,4237.99 3482.01,4237.99 3682.01,4237.99 3882.01,4237.99 4082.01,4237.99 4882.01,4237.99 5082.01,4237.99 5282.01,4237.99 5482.01,4237.99 5685,4290 5912.99,4292.01 4310,4300 4460,4300 4610,4300 6090,4305 6360,4369.45 4310,4415 4460,4415 4610,4415 3282.01,4437.99 3482.01,4437.99 3682.01,4437.99 3882.01,4437.99 4082.01,4437.99 7847.01,4442.99 5282.01,4452.99 5482.01,4452.99 4752.01,4462.99 4952.01,4462.99 5152.01,4462.99 5687.01,4492.99 6072.01,4492.99 5915,4495 6352.01,4502.99 6577.01,4502.99 6832.01,4502.99 7032.01,4502.99 7232.01,4502.99 6855,4605 6290,4610 6420,4610 6590,4610 6710,4610 4310,4615 4460,4615 4610,4615 3282.01,4637.99 3482.01,4637.99 3682.01,4637.99 3882.01,4637.99 4082.01,4637.99 7232.01,4642.99 7512.01,4642.99 7632.01,4642.99 7832.01,4642.99 5282.01,4652.99 5482.01,4652.99 4752.01,4662.99 4952.01,4662.99 5152.01,4662.99 7022.01,4667.99 5687.01,4692.99 6072.01,4692.99 5915,4695 6522.01,4702.99 6792.01,4707.99 6267.01,4717.99 4310,4815 4460,4815 4610,4815 3282.01,4837.99 3482.01,4837.99 3682.01,4837.99 3882.01,4837.99 4082.01,4837.99 5282.01,4852.99 5482.01,4852.99 4752.01,4862.99 4952.01,4862.99 5152.01,4862.99 5915,4865 4205,4880 5687.01,4892.99 6072.01,4892.99 6641.91,4945.55 6836.91,4945.55 7041.91,4945.55 7241.91,4945.55 7641.91,4945.55 6558.92,4947.56 6758.92,4947.56 6958.92,4947.56 7158.92,4947.56 7558.92,4947.56 7758.92,4947.56 7958.92,4947.56 7343.92,4952.56 4038.1,4986.9 4230,5010 4610,5015 3282.01,5037.99 3482.01,5037.99 3682.01,5037.99 5882.01,5037.99 4092.01,5052.99 5282.01,5052.99 5482.01,5052.99 5662.01,5052.99 4952.01,5062.99 5152.01,5062.99 4395,5065 6155,5090 5995,5170 7610,5180 5485,5225 5685,5225 4460,5235 3282.01,5237.99 3482.01,5237.99 3682.01,5237.99 4082.01,5237.99 4755,5250 4955,5250 5155,5250 5882.01,5267.99 4625,5295 7492.63,5312.99 6015,5350 6215,5350 6415,5350 6615,5350 6815,5350 7015,5350 4280,5385 4915,5420 7380,5420 3282.01,5437.99 3482.01,5437.99 3682.01,5437.99 4082.01,5437.99 5882.01,5437.99 6015,5445 6215,5445 6415,5445 6615,5445 6815,5445 7015,5445 4700,5455 5100,5455 5300,5455 5500,5455 5700,5455 7620.25,5556.49 6217.63,5560.74 6417.63,5560.74 6617.63,5560.74 6817.63,5560.74 7017.63,5560.74 7217.63,5560.74 7417.63,5560.74 5015,5565 5215,5565 5415,5565 5615,5565 5815,5565 6015,5565 4281,5567.5 4444,5569.51 3282.01,5637.99 3482.01,5637.99 3682.01,5637.99 4082.01,5637.99 6417.63,5697.99 6617.63,5697.99 6817.63,5697.99 7017.63,5697.99 7217.63,5697.99 7417.63,5697.99 7617.63,5697.99 6229.63,5698.74 5212.63,5700.74 5427.01,5702.99 5627.01,5702.99 5827.01,5702.99 6027.01,5702.99 5010,5705 4449,5709.51 4281,5712.5 7622.63,5835.74 3282.01,5837.99 3482.01,5837.99 3682.01,5837.99 3882.01,5837.99 6220,5840 6420,5840 6620,5840 6820,5840 7020,5840 7220,5840 7420,5840 4282.01,5867.99 4445,5870 4625,5872.21 4825,5872.21 5872.01,5872.99 5015,5875 5215,5875 5415,5875 5615,5875 4450,6020 4630,6022.21 4830,6022.21 4282.01,6022.99 5020,6025 5220,6025 5420,6025 5620,6025 3282.01,6037.99 3482.01,6037.99 3682.01,6037.99 3882.01,6037.99 5882.01,6037.99 7341.91,6045.55 6340,6069.19 6445,6069.19 6540,6070 6640,6070 6745,6070 6840,6070.81 6945,6070.81 7040,6070.81 7145,6070.81 7436.91,6105.55 7358.92,6107.56 7558.92,6107.56 7758.92,6107.56 3970,6135 3282.01,6237.99 3482.01,6237.99 3682.01,6237.99 4482.01,6237.99 4682.01,6237.99 5882.01,6237.99 4840,6248.61 5030,6251.39 5230,6251.39 5430,6251.39 7410,6255 5540,6260 6260,6300 4285,6335 4395,6335 5990,6370 6190,6370 6530,6370 6730,6370 6930,6370 7130,6370 7330,6370 3282.01,6437.99 3482.01,6437.99 3682.01,6437.99 4682.01,6437.99 5082.01,6437.99 5482.01,6437.99 6092.01,6442.99 6292.01,6442.99 6577.01,6442.99 6832.01,6442.99 7032.01,6442.99 7232.01,6442.99 7432.01,6442.99 7632.01,6442.99 3282.01,6637.99 3482.01,6637.99 3682.01,6637.99 3882.01,6637.99 5082.01,6637.99 5482.01,6637.99 5882.01,6637.99 6282.01,6637.99 6577.01,6642.99 6832.01,6642.99 7032.01,6642.99 7232.01,6642.99 7432.01,6642.99 7562.01,6642.99 3925,6670 3965,6670 4054.24,6695.36 4093.61,6695.36 4129.24,6695.36 4168.61,6695.36 3925,6709.37 3965,6710 4053.61,6735.36 4093.61,6735.36 4128.61,6735.36 4168.61,6735.36 3925,6745 3965,6745 3925,6784.37 3965,6785 5132.01,6787.99 4837.01,6807.98 5012.01,6833.68 3282.01,6837.99 4482.01,6837.99 4682.01,6837.99 6832.01,6842.99 7032.01,6842.99 7232.01,6842.99 7432.01,6842.99 7562.01,6842.99 5217.01,6847.99 5592.01,6847.99 5767.01,6847.99 6327.01,6847.99 6492.01,6847.99 5930,6850 6127.01,6852.99 5387.01,6853.68 3282.01,7037.99 3482.01,7037.99 4282.01,7037.99 4482.01,7037.99 4682.01,7037.99 5547.01,7037.99 5882.01,7037.99 6282.01,7037.99 6667.01,7042.99 6832.01,7042.99 7032.01,7042.99 7232.01,7042.99 7432.01,7042.99 7632.01,7042.99 3282.01,7237.99 6832.01,7242.99 7032.01,7242.99 7232.01,7242.99 7432.01,7242.99 7632.01,7242.99 7832.01,7242.99 5682.01,7267.99 5882.01,7267.99 6082.01,7267.99 6282.01,7267.99 6667.01,7272.99 5422.01,7277.99 5097.01,7317.99 7812.01,7417.99 3282.01,7437.99 3482.01,7437.99 3707.01,7437.99 3882.01,7437.99 4082.01,7437.99 4282.01,7437.99 4482.01,7437.99 4682.01,7437.99 6832.01,7442.99 7032.01,7442.99 7232.01,7442.99 7432.01,7442.99 7632.01,7442.99 6667.01,7472.99 4882.01,7542.99 5082.01,7542.99 5282.01,7542.99 5482.01,7542.99 5682.01,7542.99 5882.01,7542.99 6282.01,7542.99 6182.01,7552.99
GND_ISO: C12.1 C13.2 C16.1 C18.1 C20.1 P4.8 R22.1 U11.3 U13.5 | length 616.4
  Top Layer w20: U13.5@6557.18,4074.05 6562.18,4069.05 v2(6562.18,4000) ; v3(6725.16,4030) C20.1 ; v3(6841.02,4030) C18.1@6841.02,4121.49 ; C12.1 v3@7510,3901.81 ; v3(7660,3945) 7660.24,3944.76 C13.2@7660.24,3865
  Top Layer w30: v2(7225,4230) 7301.66,4230 R22.1@7303,4228.66 ; v2(7395,4238.37) C16.1
  Top Layer w40: v2(7535,4255) 7605.01,4255 U11.3
  other v1: 6722.01,3097.99 6922.01,3097.99 7122.01,3097.99 7322.01,3097.99 7522.01,3097.99 7722.01,3097.99 7922.01,3097.99 6722.01,3297.99 6957.01,3297.99 7122.01,3297.99 7322.01,3297.99 7522.01,3297.99 7692.01,3297.99 7922.01,3297.99 6722.01,3497.99 6957.01,3497.99 7122.01,3497.99 7322.01,3497.99 7522.01,3497.99 7692.01,3497.99 7922.01,3497.99 7692.01,3667.99 6957.01,3697.99 7122.01,3697.99 7322.01,3697.99 7522.01,3697.99 7922.01,3697.99 6957.01,3897.99 7122.01,3897.99 7922.01,3897.99 6922.01,4097.99 7322.01,4097.99 7522.01,4097.99 7722.01,4097.99 7922.01,4097.99
  other v3: 7510,3905
GPIO0: CN9.3 P2.7 P6.7 | length 4075.3
  Top Layer w10: v3(5965,4165) 5965,4040 6248.43,3756.57 CN9.3 ; v3(5965,4355) 5955,4365 5955,5713.8 6286.2,6045 7210,6045 7250,6085 7250,6141.36 P6.7@7290.55,6181.91 ; P2.7@7283.09,5961.91 P2.7@7290.55,5961.91
  Bottom Layer w10: v3(5965,4165) v3(5965,4355) ; P2.7 P6.7
GPIO1: P2.8 P6.8 R2.1 | length 2708
  Top Layer w10: R2.1 5260.63,6100 7105,6100 7186.92,6181.92 P6.8
  Bottom Layer w10: P2.8 P6.8
GPIO2: P2.12 P6.12 | length 220
  Bottom Layer w10: P2.12 P6.12
GPIO3: CN6.3 P2.13 P6.13 R18.2 | length 4945.2
  Top Layer w10: CN6.3 3608.43,3743.43 3640,3775 3729.66,3775 v3(3745,3790.34)
  Bottom Layer w10: v3(3745,3790.34) 3760,3805.34 3760,4605 4900,5745 6580,5745 6690.55,5855.55 P2.13 P6.13
GPIO4: P2.3 P6.3 R3.2 | length 1741.6
  Top Layer w10: R3.2 6380,6470.63 7554.37,6470.63 7690.55,6334.45 P6.3@7690.55,6186.92
  Bottom Layer w10: P2.3 P6.3
GPIO5: P2.4 P6.4 R13.2 | length 1971.1
  Top Layer w10: R13.2 6070.63,6405 7442.47,6405 7590.55,6256.92 P6.4@7590.55,6186.92
  Bottom Layer w10: P2.4 P6.4
GPIO6: P2.5 P6.5 R15.2 | length 2226.1
  Top Layer w10: R15.2 5774.37,6475.63 5915,6335 7412.47,6335 7490.55,6256.92 P6.5@7490.55,6186.92
  Bottom Layer w10: P2.5 P6.5
GPIO7: P2.6 P6.6 R17.1 | length 2464.6
  Top Layer w10: R17.1 5359.37,6475.63 5570,6265 7320,6265 7390.55,6194.45 P6.6@7390.55,6186.92
  Bottom Layer w10: P2.6 P6.6
GPIO8: P2.9 P6.9 | length 220
  Bottom Layer w10: P2.9 P6.9
GPIO9: P1.6 P5.6 | length 209.5
  Bottom Layer w10: P5.6@6892.54,4856.89 P1.6@6892.54,5066.38
GPIO10: P2.10 P6.10 | length 220
  Bottom Layer w10: P2.10 P6.10
GPIO11: P2.11 P6.11 | length 250
  Bottom Layer w10: P2.11@6890.55,5931.91 P6.11
GPIO12: P1.3 P5.3 | length 209.5
  Bottom Layer w10: P5.3@6592.54,4856.89 P1.3@6592.54,5066.38
GPIO13: P1.4 P5.4 | length 209.5
  Bottom Layer w10: P5.4@6692.54,4856.89 P1.4@6692.54,5066.38
GPIO15: P1.13 P5.13 | length 209.5
  Bottom Layer w10: P5.13@7592.54,4856.89 P1.13@7592.54,5066.38
GPIO16: P1.15 P5.15 | length 209.5
  Bottom Layer w10: P5.15@7792.54,4856.89 P1.15@7792.54,5066.38
GPIO17: CN4.3 P1.14 P5.14 | length 5548.3
  Bottom Layer w10: CN4.3 4148.43,3703.43 4258.53,3813.53 4258.53,3827.67 4258.11,3828.09 4258.11,3847.89 4259.21,3848.99 4259.21,4850.21 4897.09,5488.09 7471.91,5488.09 7695.43,5264.57 7695.43,5069.28 7692.54,5066.4 P5.14@7692.54,4856.89
GPIO18: P1.7 P5.7 U13.3 | length 1883.2
  Top Layer w10: v1(6226.36,4124.36) 6226.67,4124.05 U13.3@6354.82,4124.05
  Bottom Layer w10: v1(6226.36,4124.36) 6200.64,4124.36 6140,4185 6140,4565 6235,4660 6915,4660 7005,4750 7005,4854.44 7002.54,4856.9 7002.54,5056.38 P1.7@6992.54,5066.38
GPIO18_ISO: P3.5 U13.6 | length 721.3
  Top Layer w10: U13.6@6557.18,4124.05 6595.95,4124.05 6625,4095 6625,3800 P3.5@6870,3555
GPIO19: P1.8 P5.8 U13.2 | length 1862.7
  Top Layer w10: v1(6259.66,4169.85) 6350.62,4169.85 U13.2@6354.82,4174.05
  Bottom Layer w10: v1(6259.66,4169.85) 6225.15,4169.85 6195,4200 6195,4490 6267.07,4562.07 7022.07,4562.07 7100,4640 7100,4854.35 7102.54,4856.9 7102.54,5056.38 P1.8@7092.54,5066.38
GPIO19_ISO: P3.6 U13.7 | length 691.3
  Top Layer w10: U13.7@6557.18,4174.05 6630,4174.05 6662.03,4142.03 6662.03,3862.97 P3.6@6870,3655
GPIO20: CN8.4 P1.9 P5.9 | length 3048.2
  Top Layer w10: CN8.4 5801.02,3618.39 5801.02,3703.98 v3(5800,3705)
  Bottom Layer w10: v3(5800,3705) 5800,4015 5775,4040 5775,4800 6140,5165 7145,5165 7195,5115 7195,5068.85 7192.54,5066.4 P5.9@7192.54,4856.89
GPIO21: CN8.3 P1.10 P5.10 | length 3512
  Top Layer w10: CN8.3 5700.34,3616.12 5700.34,3704.66 v3(5700,3705)
  Bottom Layer w10: v3(5700,3705) 5570,3835 5570,4860 5945,5235 7215,5235 7295,5155 7295,5068.85 7292.54,5066.4 P5.10@7292.54,4856.89
GPIO22: CN7.3 P1.11 P5.11 | length 4197.6
  Bottom Layer w10: CN7.3@5209.9,3549.99 5209.9,5134.9 5375,5300 7250,5300 7395,5155 7395,5068.85 7392.54,5066.4 P5.11@7392.54,4856.89
GPIO23: CN5.3 P1.12 P5.12 | length 4854.8
  Bottom Layer w10: CN5.3 4685,3550.1 4685,5025 5065,5405 7265,5405 7490,5180 7490,5068.94 7492.54,5066.4 P5.12@7492.54,4856.89
PH: B_C2.1 B_D1.1 B_L1.1 B_U1.8
RST: P2.2 P6.2 | length 220
  Bottom Layer w10: P2.2 P6.2
SS: B_C3.2 B_U1.4 | length 161.5
  Top Layer w10: B_C3.2 4016.23,6910 4050.37,6875.86 B_U1.4@4050.37,6824.51
VSENSE: B_R5.1 B_R6.2 B_U1.5 | length 390.5
  Top Layer w20: B_R5.1@3947.41,6296.29 3950,6298.88 3950,6565 3999.19,6614.19 B_U1.5
pads on no net: P1.1 P2.14 P2.16 P3.1 P3.2 P3.3 P3.4 P3.7 P3.8 P4.1 P4.2 P4.3 P4.4 P4.5 P4.6 P5.1 P6.14 P6.16
copper on no net: | length 440
  Bottom Layer w10: 6390.55,5961.92 6390.55,6181.92 ; 6590.55,5961.92 6590.55,6181.92

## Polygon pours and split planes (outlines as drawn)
5V on Top Layer (solid, remove dead copper, pour order 0): 4600.37,6630.37 4600.37,6380.37 4435.37,6380.37 4435.37,6630.37
GND on Top Layer (solid, remove dead copper, pour order 8): 3035,7665 8012.5,7665 8012.5,3025 3035,3025
GND_ISO on Bottom Layer (solid, remove dead copper, pour order 10): 8030,3042.94 8030,4310 6510,4310 6510,3042.94
GND on Bottom Layer (solid, remove dead copper, pour order 12): 6420,3040 3040,3040 3035,7665 8025,7660 8025,4395 6420,4395
PH on Top Layer (solid, remove dead copper, pour order 2): 4419.47,6584.05 4419.47,6370.37 4185.37,6370.37 4185.37,6635.37 4215.37,6635.37 4215.37,6550.37 4350.37,6550.37 4350.37,6584.05
GND_ISO on Top Layer (solid, remove dead copper, pour order 4): 8030,3042.94 8030,4310 6510,4310 6510,3042.94
12V on Top Layer (solid, remove dead copper, pour order 6): 4173.7,6792.14 4173.7,7315 3565,7315 3565,6970 3850,6970 3850,7065 4120,7065 4125,7060 4125,6792.14

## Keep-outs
Top Layer:
  region: 8045,4395 8045,4315 6510,4315 6510,3015 6425,3015 6425,4395
Board Outline Layer:
  circle w1: c7860,7500 r40
  region: 7900,7500 cw(c7860,7500) 7820,7500 cw(c7860,7500)
  circle w1: c7905,3200 r40
  region: 7945,3200 cw(c7905,3200) 7865,3200 cw(c7905,3200)
  circle w1: c3205,3210 r40
  region: 3245,3210 cw(c3205,3210) 3165,3210 cw(c3205,3210)
  circle w1: c3205,7500 r40
  region: 3245,7500 cw(c3205,7500) 3165,7500 cw(c3205,7500)
  region: 7740.8,5916.91 8047.61,5916.91 8047.61,5120 7740.8,5120
  lines w11.81: 3000,3000 8065,3005 8065,7705 3000,7705 3000,3000

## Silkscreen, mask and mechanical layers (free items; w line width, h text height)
Top Silkscreen Layer:
  drawing of 154 lines, arcs and shapes, not listed
  text "PP_4" at 5315,7605 h45
  text "PP_3" at 5685,7605 h45
  text "PP_2" at 6045,7605 h45
  text "PP_1" at 6430,7605 h45
  text "MAG_V 12V" at 4860,7565 h45
  text "BLOOM" at 5300,7560 h45
  text "MICRO" at 5675,7560 h45
  text "GROW" at 6041.8,7560 h45
  text "ACID" at 6435,7560 h45
  text "[-]" at 4910,7515 h45
  text "[+]" at 5020,7515 h45
  text "[-]" at 5280,7515 h45
  text "[+]" at 5390,7515 h45
  text "[-]" at 5654.7,7515 h45
  text "[+]" at 5764.7,7515 h45
  text "[-]" at 6024.7,7515 h45
  text "[+]" at 6134.7,7515 h45
  text "[-]" at 6394.7,7515 h45
  text "[+]" at 6504.7,7515 h45
  text "v0.1" at 7340,6860 h80
  text "5V" at 4635,6460 h60
  text "4" at 7755,6270 h100 r90
  text "NC" at 6445,6269.45 h100 r90
  text "GND" at 6549.99,6269.44 h100 r90
  text "NC/5V" at 6644.99,6269.44 h100 r90
  text "3" at 6744.99,6269.44 h100 r90
  text "2" at 6849.99,6269.44 h100 r90
  text "11" at 6944.99,6269.44 h100 r90
  text "10" at 7044.99,6269.44 h100 r90
  text "8" at 7150,6269.45 h100 r90
  text "1" at 7245,6269.45 h100 r90
  text "0" at 7345,6269.45 h100 r90
  text "7" at 7450,6269.45 h100 r90
  text "6" at 7545,6269.45 h100 r90
  text "5" at 7645,6269.45 h100 r90
  text "ANTENNA" at 8025,5315 h80 r90
  text "9" at 6950,4729.45 h100 r90
  text "12" at 6650,4699.45 h100 r90
  text "13" at 6750,4699.45 h100 r90
  text "19" at 7150.01,4699.45 h100 r90
  text "18" at 7050.01,4694.45 h100 r90
  text "15" at 7650,4694.45 h100 r90
  text "17" at 7750,4694.45 h100 r90
  text "16" at 7850.01,4694.45 h100 r90
  text "21" at 7350,4689.45 h100 r90
  text "NC" at 6450,4669.45 h100 r90
  text "20" at 7250,4669.45 h100 r90
  text "22" at 7450.01,4669.45 h100 r90
  text "23" at 7550.01,4669.45 h100 r90
  text "GND" at 6550,4610 h100 r90
  text "GND" at 6850,4609.45 h100 r90
  text "GND" at 7950.01,4604.45 h100 r90
  text "EZO PH" at 7835,3805 h80 r270
  text "GND" at 3350,3175 h45
  text "3V3" at 3470,3175 h45
  text "SIG(4K7+)" at 3590,3175 h45
  text "GND" at 3890,3175 h45
  text "3V3" at 4010,3175 h45
  text "SIG" at 4130,3175 h45
  text "GND" at 4426.46,3175 h45
  text "3V3" at 4546.46,3175 h45
  text "SIG" at 4666.46,3175 h45
  text "GND" at 4951.46,3175 h45
  text "3V3" at 5071.46,3175 h45
  text "SIG" at 5191.46,3175 h45
  text "GND" at 5989.92,3175 h45
  text "3V3" at 6109.92,3175 h45
  text "SIG" at 6229.92,3175 h45
  text "SIG" at 5762.45,3142.5 h45
  text "3V3" at 5450,3140 h45
  text "GND" at 5555,3140 h45
  text "SIG" at 5670,3140 h45
  text "WTR_TEMP" at 3355,3085 h80
  text "WTR_LO" at 4425,3085 h80
  text "WTR_EMPTY" at 4860,3085 h80
  text "WTR_HI" at 3890,3080 h80
  text "WTR_TDS" at 5989.92,3080 h80
  text "AIR_TEMP" at 5450,3070 h80
Mechanical Layer:
  circle w1: c7860,7500 r40
  circle w1: c7905,3200 r40
  circle w1: c3205,3210 r40
  circle w1: c3205,7500 r40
